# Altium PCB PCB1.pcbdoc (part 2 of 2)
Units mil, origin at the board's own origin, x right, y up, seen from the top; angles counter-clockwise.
Board outline 29590.16 x 26896.25 mil, 2 copper layers (Top Layer, Bottom Layer); 414 components, 328 nets, 1399 pads, 0 vias.
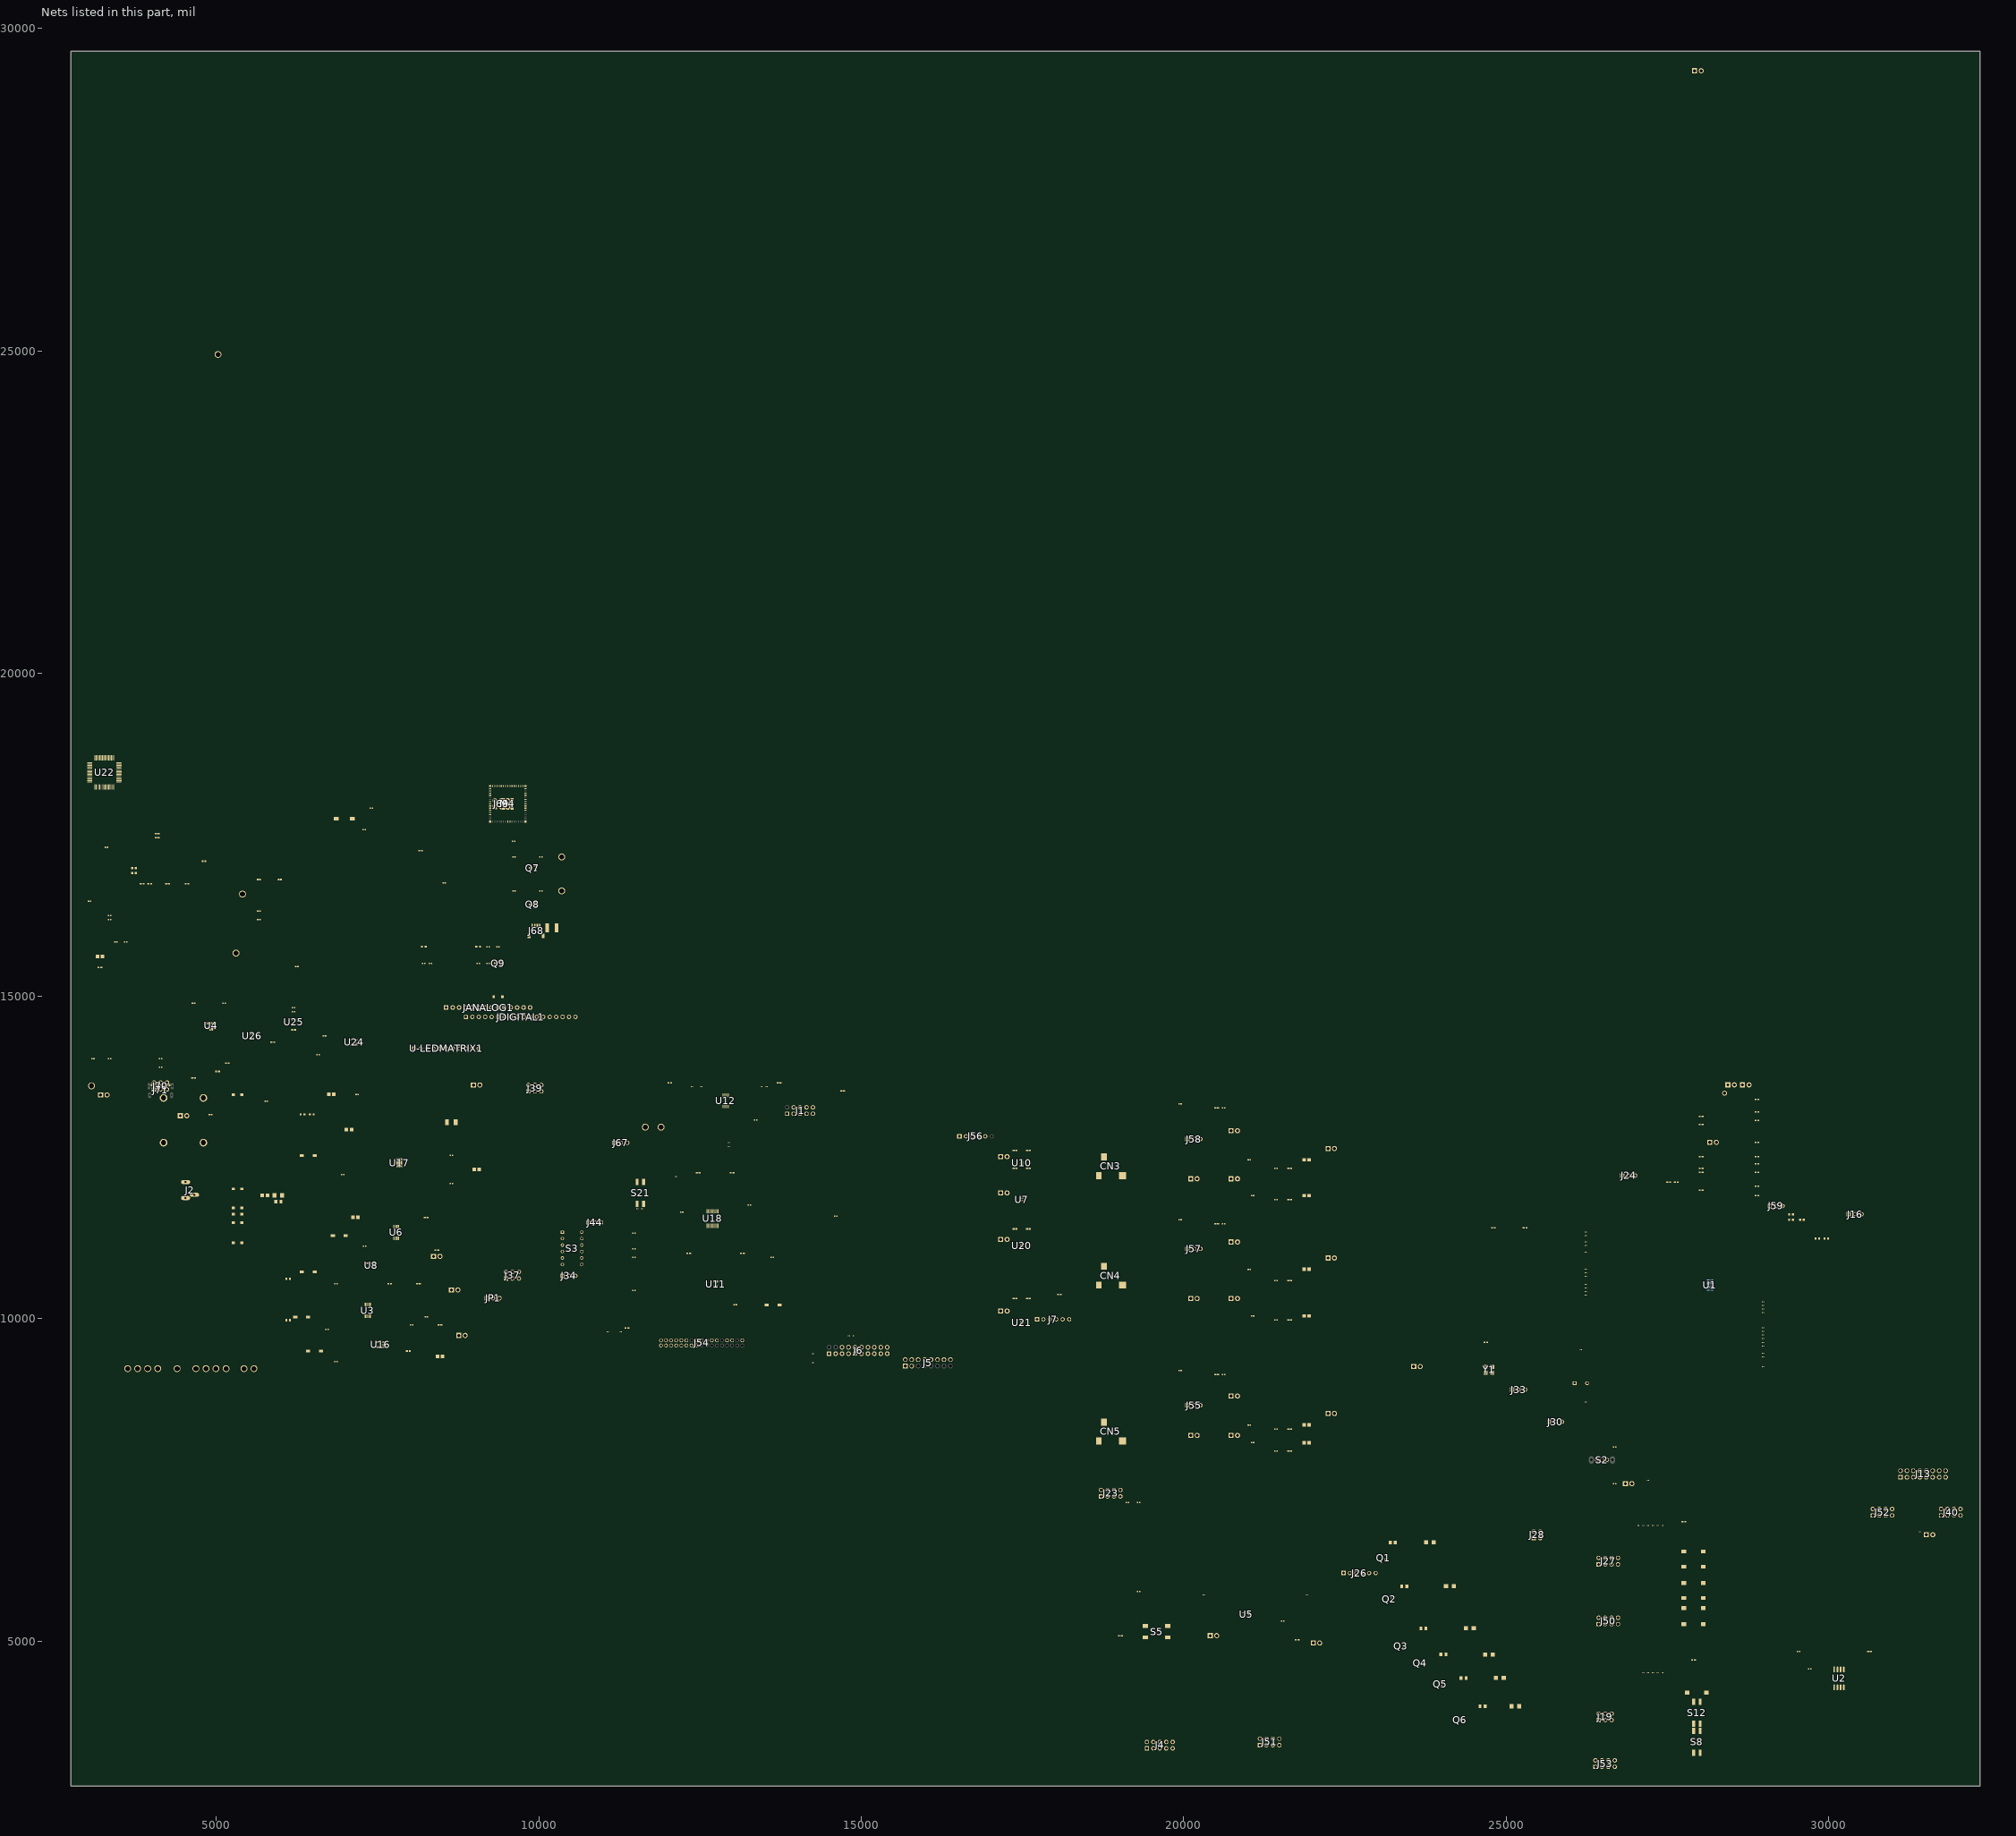
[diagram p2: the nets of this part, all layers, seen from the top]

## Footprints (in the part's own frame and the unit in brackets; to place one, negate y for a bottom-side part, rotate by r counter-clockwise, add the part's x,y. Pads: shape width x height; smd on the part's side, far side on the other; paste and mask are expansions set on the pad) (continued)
SW-SMD_L6.0-W6.0-LS6.6 [mm]
  rect 1.985x1.512 smd: 1(-3.193,0) 2(3.193,0)
  silkscreen extent -3.33,-3.08 3.33,3.08
SW-TH_SS12D07VG4 [mm]
  round 1.6 hole 1: 1(-2,0) 2(0,0) 3(2,0)
  oval 2x3 hole 1 slot 1.8 at 90 deg: 4(4.15,0) 5(-4.15,0)
  silkscreen extent -4.4,-2.3 4.4,2.3
SW_1-1825010-3 [mm]
  rect 1.298x1.298 hole 0.79: 1(-3.81,6.35)
  round 1.298 hole 0.79: 2(-3.81,3.81) 3(-3.81,1.27) 4(-3.81,-1.27) 5(-3.81,-3.81) 6(-3.81,-6.35) 7(3.81,-6.35) 8(3.81,-3.81) 9(3.81,-1.27) 10(3.81,1.27) 11(3.81,3.81) 12(3.81,6.35)
  silkscreen extent -5.28,-8.89 3.68,8.89
TESTPOINT-TH_BD2.5-D1.2_RH-5002 [mm]
  round 1.9 hole 1.2: 1(0,0)
  silkscreen extent -1.27,-1.27 1.27,1.27
TESTPOINT-TH_BD3.2 [mm]
  round 2.7 hole 2: 1(0,0)
  silkscreen extent -1.6,-1.6 1.6,1.6
TSOT-5_L2.9-W1.6-P0.95-LS2.8-BR [mm]
  rect 1x0.5 smd: 1(1.399,-0.95) 2(1.401,0) 3(1.398,0.95) 4(-1.401,0.95) 5(-1.401,-0.95)
  silkscreen extent -1.1,-1.72 2.39,1.63
TSOT-23-5_L2.9-W1.6-P0.95-LS2.8-BR [mm]
  rect 1.1x0.7 smd: 1(1.294,-0.951) 2(1.294,-0.001) 3(1.294,0.951) 4(-1.294,0.951) 5(-1.294,-0.949)
  silkscreen extent -0.97,-1.65 1.52,1.61
TSSOP-16_L5.0-W4.4-P0.65-LS6.4-BL [mil]
  oval 13.5x68.17 smd: 1(-89.57,-112.83) 2(-63.98,-112.83) 3(-38.39,-112.83) 4(-12.79,-112.83) 5(12.8,-112.83) 6(38.39,-112.83) 7(63.98,-112.83) 8(89.57,-112.83) 9(89.57,112.83) 10(63.98,112.83) 11(38.39,112.83) 12(12.8,112.83) 13(-12.79,112.83) 14(-38.39,112.83) 15(-63.98,112.83) 16(-89.57,112.83)
  silkscreen extent -120,-119 101,70
USB-C-SMD_CX90B-16P [mm]
  oval 1.1x2.6 hole 0.6 slot 2 at 90 deg: 0(-4.62,1.563) 0(4.62,1.563)
  oval 1.2x2.3 hole 0.6 slot 1.7 at 90 deg: 1(-4.32,-1.987) 1(4.32,-1.987)
  round 0.75 hole 0.45: 2(-3.32,0.988) 3(3.32,0.988)
  rect 0.57x0.85 smd: A1(-3.635,1.987) A12(3.635,1.987)
  rect 0.25x0.85 smd: A4(-2.275,1.987) A9(2.275,1.987) B1(3.025,1.987) B4(1.825,1.987) B9(-1.825,1.987) B12(-3.025,1.987)
  rect 0.2x0.85 smd: A5(-1.4,1.987) A6(-0.6,1.987) A7(0.6,1.987) A8(1.4,1.987) B5(1,1.987) B6(0.2,1.987) B7(-0.2,1.987) B8(-1,1.987)
  silkscreen extent -4.45,-4.19 4.5,2.8

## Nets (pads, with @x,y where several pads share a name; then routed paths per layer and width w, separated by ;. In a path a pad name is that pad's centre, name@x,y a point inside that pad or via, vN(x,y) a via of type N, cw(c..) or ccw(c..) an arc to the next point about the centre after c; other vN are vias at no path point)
1715_EN: R70.2 R71.2 S18.2 S20.2 U3.2 U8.3
5302_EN: R73.2 S1.2 U17.1
5335_EN: R72.2 S19.2 U6.6
$1N1953: R24.2 S2.1
$1N1981: R76.1 S2.3
$1N2920: C9.1 C21.1 C55.1 C56.1 J12.2 U1.A3 U1.F1 U1.F7
$1N5576: R77.2 S2.2 U1.F2
$1N8257: J41.2 R77.1
$1N8528: J32.2 Y1.1
$1N8935: C3.2 R3.1 Y2.2
$1N8973: C5.2 J30.3 Y2.1
$1N10228: C13.1 C41.1 U1.L5
$1N11371: J59.3 R13.1 U1.J1
$1N11410: J59.1 R12.1 U1.L1
$1N11460: C4.2 C15.2 J16.1 R13.2 U1.J2
$1N11465: C15.1 C32.2 J16.3 R12.2 U1.K2
$1N14235: J25.1 J48.1 J58.1 R42.1
$1N14294: J58.3 R116.1
$1N14477: J11.1 R44.1
$1N14540: CN3.2 J58.2
$1N14654: CN3.3 J11.2 J25.2 R75.1
$1N14795: C1.1 C33.2 R41.2 R42.2
$1N14914: C28.2 C29.1 R74.2 R75.2
$1N15076: C1.2 J64.1
$1N15904: J42.1 J46.1 J57.1 R48.1
$1N15917: J57.3 R115.1
$1N15921: J14.1 R50.1
$1N15923: CN4.2 J57.2
$1N15927: CN4.3 J14.2 J42.2 R79.1
$1N15937: C2.1 C38.2 R47.2 R48.2
$1N15948: C30.2 C31.1 R78.2 R79.2
$1N15959: C2.2 J65.1
$1N16727: J43.1 J47.1 J55.1 R53.1
$1N16740: J55.3 R107.1
$1N16744: J21.1 R59.1
$1N16746: CN5.2 J55.2
$1N16750: CN5.3 J21.2 J43.2 R54.1
$1N16760: C17.1 C43.2 R52.2 R53.2
$1N16771: C19.1 C46.2 R54.2 R55.2
$1N16782: C17.2 J66.1
$1N17614: C24.2 R25.1 S5.2
$1N17727: J10.2 S5.3
$1N17731: J10.1 R10.1 S5.1 U5.2
$1N17839: R36.2 U5.4
$1N18363: R111.2 U2.1
$1N19695: J49.1 R29.2
$1N20097: J4.9 R30.2
$1N20304: J26.1 Q1.1
$1N20401: Q1.3 R63.2
$1N20491: D7.1 R63.1
$1N20673: Q2.3 R108.2
$1N20676: D10.1 R108.1
$1N20958: Q3.3 R109.2
$1N20961: D8.1 R109.1
$1N21371: Q4.3 R110.2
$1N21374: D9.1 R110.1
$1N21378: Q5.3 R105.2
$1N21381: D11.1 R105.1
$1N21385: Q6.3 R106.2
$1N21388: D12.1 R106.1
$1N21398: J26.2 Q2.1
$1N21405: J26.3 Q3.1
$1N21412: J26.4 Q4.1
$1N21420: J26.5 Q5.1
$1N21426: J26.6 Q6.1
$1N21553: D7.2 D8.2 D9.2 D10.2 D11.2 D12.2 J28.2 J28.4
$1N23160: J27.2 R66.1 S13.1
$1N23619: J27.4 R21.1 S14.1
$1N23625: J27.6 R39.1 S15.1
$1N23631: J27.8 R67.1 S16.1
$1N23637: J50.4 R40.1 S9.1
$1N23643: J50.6 R65.1 S10.1
$1N24875: J50.2 R64.1 S11.1
$1N24884: J50.8 R60.1 S12.1
$1N24995: J19.2 R61.1 S12.2
$1N25008: J19.4 R20.1 S8.1
$1N25013: J19.6 R62.1 S8.2
$2N681: R38.2 U18.10
$2N697: R130.2 U18.7
$2N1616: R94.2 U12.5
$2N7921: R14.1 R22.1 U18.13
$2N7925: R16.1 U11.3
$2N7967: R19.1 U18.12
$2N7974: R17.1 U18.11
$2N8059: J44.3 S3.2
$2N8118: J34.3 S3.11
$2N10821: J6.11 R98.2
$2N10823: J6.15 R15.2
$2N10825: J6.17 R97.2
$2N14979: J60.1 U10.4
$2N15027: J61.1 U7.4
$2N15536: J62.1 U20.4
$2N15539: J63.1 U21.4
$3N506: D3.2 J2.5
$3N1554: D13.2 R58.2
$3N4375: L1.1 U17.9
$3N4413: R69.1 U17.6
$3N4489: R68.2 U17.4
$3N4842: J29.1 J39.1
$3N5510: C52.1 U6.5
$3N5995: C60.2 U8.4
$3N8224: R1.1 R2.2 U3.4
$3N8455: J3.1 JP1.3
$3N8798: R101.2 S6.2 U16.3
$3N8977: C49.1 U16.4
$3N8981: C49.2 C53.2 J45.2 U16.5
$4N19290: C78.2 U22.20
$4N19292: L3.2 U22.59
$4N19293: C79.2 C81.2 L2.2 U22.56
$4N19297: C80.2 U22.4
$4N19298: C82.2 U22.5
$4N19314: R135.1 R136.2
$4N19317: R134.1 R135.2 U22.16
$4N19362: R137.1 U22.27
$4N19372: TP6.1 U22.38
$4N19383: R139.1 R140.2 U22.49
$4N19492: M4.7 R148.1 R149.2
$4N19507: M4.40 R151.1
$4N19510: M4.39 R152.1
$4N19539: R153.1 U4.6
$4N19546: R157.2 U4.11
$4N19547: R156.2 U4.12
$4N19548: R155.2 U4.18
$4N19549: R154.2 U4.19
$4N19643: DL2.1 R166.2 R167.2
$4N19647: DL1.1 R168.2
$4N19648: DL3.2 R170.2
$4N19649: DL4.1 R169.2
$4N19653: Q9.3 R169.1
+1V2: C59.2 J37.5 U8.5
+1V8: C34.2 C40.2 C75.2 J9.1 J13.15 J17.1 J37.3 J39.2 J39.4 J39.6 R44.2 R50.2 R59.2 R107.2 R115.2 R116.2
+1V8_REG_LIN: C51.1 C52.2 J39.5 U6.1 U6.2 U6.3
+1V8_REG_SW: C27.2 J39.3 L1.2 R69.2 U17.5
+3V3: C47.1 C57.1 C62.1 C68.2 C69.2 C70.2 C71.2 C83.2 C84.2 C85.2 DL2.2 F1.2 J28.1 J45.1 JANALOG1.4 M4.3 R92.2 R93.2 R104.1 R148.2 R150.1 R153.2 U4.5 U7.1 U10.1 U10.5 U11.6 U12.8 U18.1 U20.1 U20.5 U21.1
+3V3_I2C: F1.1 J68.2 Q7.1 Q8.1 R141.2 R143.2
+4V5: C18.2 C26.2 C50.1 C58.2 C66.2 C76.2 C77.2 C86.2 C87.2 C88.2 C89.2 D1.1 D2.1 D3.1 D4.1 D5.1 D6.1 D13.1 D14.1 DL1.2 DL3.1 DL4.2 J28.3 J69.2 JANALOG1.2 JANALOG1.5 L2.1 R133.2 R134.2 R137.2 R138.2 R139.2 R142.2 R144.2 R145.2 R146.2 R147.2 S1.1 S6.1 S18.1 S19.1 S20.1 SJ1.1 U3.1 U4.16 U6.7 U6.8 U8.1 U16.1 U17.3 U17.10 U22.11 U22.21 U22.39 U25.5 U26.5
+5V_AARDVARK: C22.2 D2.2 J1.4
+5V_EXT: D1.2 J36.2 J38.1 J38.2
+5V_JTAG: D5.2 J6.19
+5V_PROMIRA: D4.2 J54.4 J54.6
+5V_UART: C44.2 D6.2 J7.6
ADDR0: R23.2 S3.7 S21.1
ADDR0/SS: S3.8 U1.D3
ADDR1: R18.2 S3.4 S21.2
ADDR1/MOSI: S3.5 U1.F3
AIN0+: J64.2 U1.L7
AIN0-: C29.2 U1.L6
AIN1+: J65.2 U1.K6
AIN1-: C31.2 U1.K5
AIN2+: J66.2 U1.K4
AIN2-: C19.2 U1.L4
AREF: JDIGITAL1.16 L3.1 R133.1
AVDD_1797: C11.2 C14.2 C42.2 J17.2 J24.1 TP5.1 U1.K7 U1.L3
BCLK_0/MP2: J27.7 J40.5 J52.5 R5.2
BCLK_0_1797: R5.1 U1.G7
BCLK_1/MP6: J4.3 J50.3 J51.3 R27.2
BCLK_1_1797: R27.1 U1.A5
BRD_RESET: J1.6 R25.2
CC1: J71.A5 R163.2
CC2: J71.B5 R164.2
CP1+: C37.1 U1.H2
CP1-: C37.2 U1.H3
CP2+: C39.1 U1.G1
CP2-: C39.2 U1.G2
CTS_UART: J7.4 U21.3
DBGRQ: R97.1
DMIC01/MP8: J13.1 J19.1 R43.2
DMIC01_1797: R43.1 U1.C6
DMIC23/MP9: J13.3 J19.3 R45.2
DMIC23_1797: R45.1 U1.D6
DMIC45/MP10: J13.5 J19.5 R46.2
DMIC45_1797: R46.1 U1.D5
DMIC67/MP11: J13.9 J53.3 R51.2
DMIC67_1797: R51.1 U1.E4
DMIC89/MP12: J13.7 J53.1 R49.2
DMIC89_1797: R49.1 U1.F4
DMIC_CLK0/MP13: J13.11 J53.5 R34.2
DMIC_CLK0_1797: R34.1 U1.D7
DMIC_CLK1/MP14: J13.13 J53.7 R29.1 R35.2
DMIC_CLK1_1797: R35.1 U1.E6
DVDD: C7.1 C36.1 J12.1 JP1.2
DVDD_REG: C16.2 JP1.1 R1.2 U3.3
ESP32_ENABLE: M4.45 R150.2
ESP_DOWNLOAD: J70.4 M4.4
ESP_IO4: M4.8 U4.1
ESP_IO5: M4.9 U4.2
ESP_IO6: M4.10 U4.3
ESP_IO7: M4.11 U4.4
ESP_IO8: M4.12 U4.7
ESP_IO9: M4.13 U4.8
ESP_IO41: J70.2 M4.37
ESP_IO42: J70.1 M4.38
ESP_MTCK: M4.35
ESP_MTDO: M4.36
ESP_N: M4.23 R159.2 U26.3
ESP_P: M4.24 R158.2 U25.3
ESP_RXD0: J70.5 R151.2 U4.10
ESP_TXD0: J70.3 R152.2 R166.1 R167.1 U4.9
EXT_MCLK: J33.3 R30.1
EXT_SCL: J68.4 Q7.2 R141.1
EXT_SDA: J68.3 Q8.2 R143.1
FSYNC_0/MP3: J27.5 J40.7 J52.7 R4.2
FSYNC_0_1797: R4.1 U1.F6
FSYNC_1/MP7: J4.7 J50.7 J51.7 R26.2
FSYNC_1_1797: R26.1 U1.A6
GND: C3.1 C4.1 C5.1 C6.1 C7.2 C8.1 C9.2 C10.1 C11.1 C12.1 C13.2 C14.1 C16.1 C18.1 C20.2 C21.2 C22.1 C23.2 C24.1 C25.1 C26.1 C27.1 C28.1 C30.1 C32.1 C33.1 C34.1 C35.1 C36.2 C38.1 C40.1 C41.2 C42.1 C43.1 C44.1 C45.2 C46.1 C47.2 C48.2 C50.2 C51.2 C53.1 C54.1 C55.2 C56.2 C57.2 C58.1 C59.1 C60.1 C61.1 C62.2 C63.1 C64.1 C65.1 C66.1 C67.1 C68.1 C69.1 C70.1 C71.1 C72.1 C73.1 C74.1 C75.1 C76.1 C77.1 C78.1 C79.1 C80.1 C81.1 C82.1 C83.1 C84.1 C85.1 C86.1 C87.1 C88.1 C89.1 C90.1 CN3.1 CN4.1 CN5.1 GND1.1 GND2.1 GND3.1 GND4.1 GND5.1 GND6.1 GND7.1 GND8.1 GND9.1 GND10.1 GND11.1 GND12.1 J1.10 J2.3 J2.4 J3.2 J4.2 J4.4 J4.6 J4.8 J4.10 J5.2 J5.4 J5.6 J5.8 J5.10 J5.12 J5.14 J5.16 J6.6 J6.8 J6.10 J6.12 J6.14 J6.16 J6.18 J6.20 J7.5 J13.2 J13.4 J13.6 J13.8 J13.10 J13.12 J13.14 J13.16 J15.2 J16.2 J23.1 J23.3 J23.5 J23.7 J24.3 J29.2 J31.1 J31.2 J32.1 J35.2 J36.1 J40.2 J40.4 J40.6 J40.8 J41.1 J46.2 J47.2 J48.2 J49.2 J51.2 J51.4 J51.6 J51.8 J52.2 J52.4 J52.6 J52.8 J53.2 J53.4 J53.6 J53.8 J54.2 J54.10 J54.12 J54.16 J54.18 J54.28 J54.30 J54.34 J56.5 J59.2 J67.1 J68.1 J68.5 J68.6 J69.6 J70.6 J71.A1 J71.A12 J71.B1 J71.B12 JANALOG1.6 JANALOG1.7 JDIGITAL1.15 M4.1 M4.2 M4.42 M4.43 M4.46 M4.47 M4.48 M4.49 M4.50 M4.51 M4.52 M4.53 M4.54 M4.55 M4.56 M4.57 M4.58 M4.59 M4.60 M4.GND PB1.1 Q1.2 Q2.2 Q3.2 Q4.2 Q5.2 Q6.2 Q9.2 R2.1 R18.1 R23.1 R32.1 R33.1 R38.1 R41.1 R47.1 R52.1 R55.1 R58.1 R68.1 R70.1 R71.1 R72.1 R73.1 R74.1 R76.2 R78.1 R94.1 R101.1 R103.2 R130.1 R132.2 R136.1 R140.1 R149.1 R162.1 R163.1 R164.1 R165.1 R170.1 R171.1 S5.4 S8.3 S8.4 S9.2 S10.2 S11.2 S12.3 S12.4 S13.2 S14.2 S15.2 S16.2 S17.1 U1.A4 U1.E1 U1.E7 U1.H4 U1.J7 U1.K3 U1.L2 U2.4 U3.5 U3.6 U3.7 U3.8 U4.15 U5.3 U6.4 U7.2 U7.5 U8.2 U10.2 U11.2 U12.4 U16.2 U17.2 U17.7 U17.8 U17.11 U18.8 U18.9 U18.14 U18.15 U20.2 U21.2 U21.5 U22.8 U22.17 U22.40 U22.57 U23.1 U25.2 U26.2 Y1.2
HPVDD_1797: C12.2 C64.2 C65.2 J9.2 U1.H1 U1.K1
IOVDD: C8.2 C10.2 C20.1 C25.2 C45.1 C48.1 C61.2 C63.2 C67.2 C72.2 C73.2 C74.2 J6.1 J8.1 J37.2 J37.4 J37.6 R8.2 R9.2 R11.2 R14.2 R20.2 R21.2 R24.1 R37.2 R39.2 R40.2 R60.2 R61.2 R62.2 R64.2 R65.2 R66.2 R67.2 R90.2 R91.2 R99.2 R100.2 S21.3 S21.4 U2.8 U7.6 U10.6 U11.1 U12.1 U18.16 U20.6 U21.6 Y1.4
IOVDD_1797: C6.2 C35.2 C54.2 J8.2 U1.A1 U1.A7
IOVDD_EXT: J35.1 J37.1
IOVDD_PROMIRA: J54.22 J54.24
JTAG_TCK/MP24: J6.9 R87.1
JTAG_TCK_1797: R87.2 U1.H7
JTAG_TDI/MP25: J6.5 R89.1
JTAG_TDI_1797: R89.2 U1.G5
JTAG_TDO/MP26: J6.13 R85.1
JTAG_TDO_1797: R85.2 U1.H5
JTAG_TMS/MP23: J6.7 R88.1
JTAG_TMS_1797: R88.2 U1.G6
JTAG_TRST/MP22: J6.3 R86.1
JTAG_TRST_1797: R86.2 U1.H6
MASTER_SLAVE_SEL: R104.2 S17.2 U11.5 U18.2 U18.3
MCLK_IN: J30.1 J33.2
MD: JANALOG1.1 R138.1 TP7.1 U4.13 U22.26
MISO_USB: J1.5 R103.1 U11.4
MOSI_USB: J1.8 R132.1 U18.5
OSC: J33.1 Y1.3
P000_AN00_AMP+: JANALOG1.10 U22.64
P001_AN01_AMP-: JANALOG1.11 U22.63
P002_AN02_AMPO: JANALOG1.12 U22.62
P003: U22.61 U-LEDMATRIX1.1
P004: U22.60 U-LEDMATRIX1.2
P011: U22.58 U-LEDMATRIX1.3
P012: U22.55 U-LEDMATRIX1.4
P013: U22.54 U-LEDMATRIX1.5
P014_AN09_DAC: JANALOG1.9 U22.53
P015: U22.52 U-LEDMATRIX1.6
P100_AN22_SCL: JANALOG1.14 JDIGITAL1.18 R146.1 U22.48
P101_AN21_SDA: JANALOG1.13 JDIGITAL1.17 R147.1 U22.47
P102_SPI0_RSPCK_GPT2_B_CAN0_RX: J69.3 JDIGITAL1.14 Q9.1 R171.2 U22.46
P103_SPI0_SSL_GPT2_A_CAN0_TX: JDIGITAL1.11 U22.45
P104_IRQ01_GPT1_B: JDIGITAL1.3 U22.44
P105_IRQ00_GPT1_A: JDIGITAL1.4 U22.43
P106_GPT0_B: JDIGITAL1.5 U22.42
P107_GPT0_A: JDIGITAL1.6 U22.41
P108_SWDIO: U4.14 U22.32
P109_SCI9_TXD: R157.1 R168.1 U22.34
P110_SCI9_RXD: R156.1 U22.35
P111_GPT3_A: JDIGITAL1.7 U22.36
P112_GPT3_B: JDIGITAL1.8 U22.37
P204: U22.24 U-LEDMATRIX1.7
P205: U22.23 U-LEDMATRIX1.8
P206: U22.22 U-LEDMATRIX1.9
P212: U22.10 U-LEDMATRIX1.10
P213: U22.9 U-LEDMATRIX1.11
P300_SWCLK: U4.17 U22.33
P301_SCI2_RXD: JDIGITAL1.1 U22.31
P302_SCI2_TXD: JDIGITAL1.2 U22.30
P303_GPT7_B: JDIGITAL1.10 U22.29
P304_GPT7_A: JDIGITAL1.9 U22.28
P400_IIC0_SCL: Q7.3 R142.1 TP3.1 U22.1
P401_IIC0_SDA: Q8.3 R144.1 TP4.1 U22.2
P408: R162.2 SJ1.2 U22.15 U25.6 U26.6
P410_SPI0_MISO_GPT6_B: J69.1 JDIGITAL1.13 U22.13
P411_SPI0_MOSI_GPT6_A: J69.4 JDIGITAL1.12 U22.12
P501_SCI1_TXD: R155.1 U22.50
P502_SCI1_RXD: R154.1 U22.51
PD: C23.1 J15.1 R8.1 R10.2 R36.1 U1.G3 U5.5
QSPIM_CLK/MP15: J54.7 R80.1 U2.6
QSPIM_CLK_1797: R80.2 U1.B4
QSPIM_CS0/MP16: J54.9 R37.1 R56.1 R111.1
QSPIM_CS0_1797: R56.2 U1.C5
QSPIM_CS1/MP17: J54.15 R57.1
QSPIM_CS1_1797: R57.2 U1.D4
QSPIM_SDIO_0/MP18: J54.8 R81.1 U2.5
QSPIM_SDIO_0_1797: R81.2 U1.A2
QSPIM_SDIO_1/MP19: J54.5 R82.1 U2.2
QSPIM_SDIO_1_1797: R82.2 U1.C4
QSPIM_SDIO_2/MP20: J54.11 R83.1 U2.3
QSPIM_SDIO_2_1797: R83.2 U1.B3
QSPIM_SDIO_3/MP21: J54.13 R84.1 U2.7
QSPIM_SDIO_3_1797: R84.2 U1.C3
RA4_N: R161.2 U22.18 U26.1
RA4_P: R160.2 U22.19 U25.1
REG_EN: J24.2 U1.J3
RESET: J69.5 JANALOG1.3 PB1.2 R15.1 R145.1 U4.20 U22.25 U23.2
RTCK: R98.1
RTS_UART: J7.1 U10.3
RXD_UART: J7.2 U7.3
SCL1: J5.1 R9.1 U1.C2
SCL_0/SCLK: J44.2 U1.C1
SCL_1797: J67.2 R90.1 R95.1 S3.1 TP1.1 U12.2
SCL_PROMIRA: J44.1 J54.1 R100.1
SCL_USB: J1.1 R93.1 R95.2 U12.7
SCLK_USB: J1.7 U18.6
SDA1: J5.3 R11.1 U1.B2
SDA_0/MISO: J34.2 U1.B1
SDA_1797: J67.3 R91.1 R96.1 S3.10 TP2.1 U12.3
SDA_PROMIRA: J34.1 J54.3 R99.1
SDA_USB: J1.3 R92.1 R96.2 U12.6
SDATAI_0/MP1: J27.3 J40.3 J52.3 R6.2
SDATAI_0_1797: R6.1 U1.F5
SDATAI_1/MP5: J4.1 J50.1 J51.1 R28.2
SDATAI_1_1797: R28.1 U1.B5
SDATAO_0/MP0: J27.1 J40.1 J52.1 R7.2
SDATAO_0_1797: R7.1 U1.E5
SDATAO_1/MP4: J4.5 J50.5 J51.5 R31.2
SDATAO_1_1797: R31.1 U1.B6
SHIELD1: C90.2 R165.2 U24.1
SPI_MISO: R16.2 S3.12
SPI_MOSI: R19.2 S3.6
SPI_SCLK: R17.2 S3.3
SPI_SS: R22.2 S3.9
SS_USB: J1.9 U18.4
TEST0: J23.6 U1.J6
TEST1: J23.2 U1.J4
TEST2: J23.4 R33.2 U1.J5
TEST_EN: J23.8 R32.2 U1.G4
TXD_UART: J7.3 U20.3
UART_CTS/MP30: J56.1 J60.2 U1.E3
UART_RTS/MP29: J56.4 J63.2 U1.D2
UART_RX/MP28: J56.3 J62.2 U1.D1
UART_TX/MP27: J56.2 J61.2 U1.E2
USB_D_N: J71.A7 J71.B7 R159.1 R161.1 U24.3 U26.4
USB_D_P: J71.A6 J71.B6 R158.1 R160.1 U24.2 U25.4
VUSB: D14.2 J71.A4 J71.A9 J71.B4 J71.B9 JANALOG1.8 TP8.1 U24.4
XTALI: J30.2 U1.B7
XTALO: R3.2 U1.C7
pads on no net: J1.2 J5.5 J5.7 J5.9 J5.11 J5.13 J5.15 J6.2 J6.4 J54.14 J54.17 J54.19 J54.20 J54.21 J54.23 J54.25 J54.26 J54.27 J54.29 J54.31 J54.32 J54.33 J56.6 J71.0 J71.1 J71.2 J71.3 J71.A8 J71.B8 M4.5 M4.6 M4.14 M4.15 M4.16 M4.17 M4.18 M4.19 M4.20 M4.21 M4.22 M4.25 M4.26 M4.27 M4.28 M4.29 M4.30 M4.31 M4.32 M4.33 M4.34 M4.41 M4.44 S2.4 S2.5 U5.1 U22.3 U22.6 U22.7 U22.14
